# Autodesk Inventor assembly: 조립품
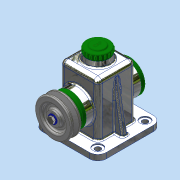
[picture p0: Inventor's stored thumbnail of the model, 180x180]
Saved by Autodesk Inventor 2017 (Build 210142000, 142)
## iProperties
Part Number: 조립품
Material: 일반
Document SubType Name: Assembly
Designer: MRC
Author: MRC
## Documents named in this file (14)
- C:\Users\MRC\Desktop\700907V1011\조립품.iam
- C:\Users\MRC\Desktop\700907V1011\V-벨트풀리.ipt
- C:\Users\MRC\Desktop\700907V1011\뒤커버.ipt
- C:\Users\MRC\Desktop\700907V1011\멈춤링 15 x 1.ipt
- C:\Users\MRC\Desktop\700907V1011\베어링 15 x 35 x 11.ipt
- C:\Users\MRC\Desktop\700907V1011\본체.ipt
- C:\Users\MRC\Desktop\700907V1011\볼트 M4 x 10.ipt
- C:\Users\MRC\Desktop\700907V1011\볼트 M6 x 12.ipt
- C:\Users\MRC\Desktop\700907V1011\상부캡.ipt
- C:\Users\MRC\Desktop\700907V1011\앞커버.ipt
- C:\Users\MRC\Desktop\700907V1011\오일실 15 25 7.ipt
- C:\Users\MRC\Desktop\700907V1011\와셔.ipt
- C:\Users\MRC\Desktop\700907V1011\축.ipt
- C:\Users\MRC\Desktop\700907V1011\키 5 x 5 x 14.ipt
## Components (1 placed, 1 different names)
1. V-벨트풀리:1
